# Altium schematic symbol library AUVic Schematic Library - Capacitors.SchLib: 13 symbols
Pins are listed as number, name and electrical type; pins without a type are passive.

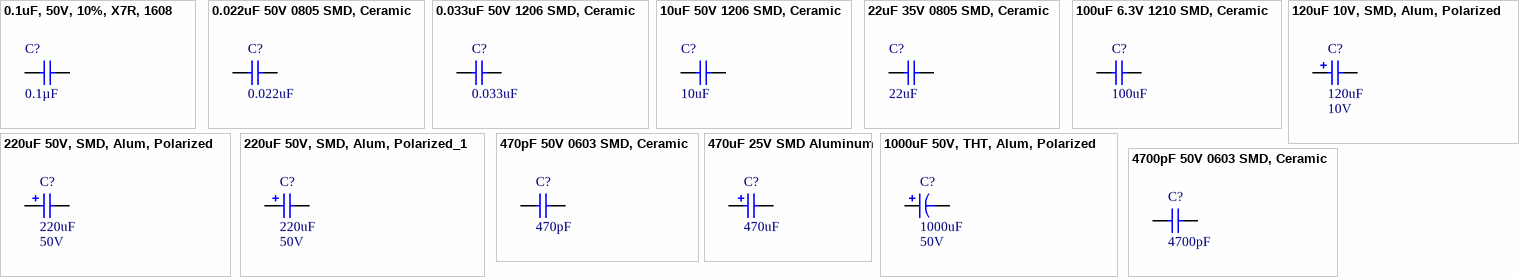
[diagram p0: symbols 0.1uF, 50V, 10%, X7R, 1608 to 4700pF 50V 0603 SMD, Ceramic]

## 0.1uF, 50V, 10%, X7R, 1608
designator C?  Capacitance: 0.1µF  (hidden comment: 0.1uF, 50V, 10%, X7R, 1608)
CAP CER 0.1UF 50V 10% X7R 1608 (0603); Manufacturer: Samsung Electro-Mechanics America, Inc; Manufacturer Part Number: CL10B104KB8SFNC; Description: CAP CER 0.1UF 50V 10% X7R 0603
footprint CAPC1608N(0603") (Chip Capacitor, Body 1.6x0.8mm (0603"), IPC Medium Density)
pins: 1, 2

## 0.022uF 50V 0805 SMD, Ceramic
designator C?, comment 0.022uF
Capacitor, Ceramic, 50V, +/-5%, 0805 SMD, X7R
footprint CAPC2012N(0805") (Chip Capacitor, Body 2.0x1.3mm (0805"), IPC Medium Density)
pins: 1, 2
1 alternate drawing of the same symbol

## 0.033uF 50V 1206 SMD, Ceramic
designator C?, comment 0.033uF
Capacitor, Ceramic, 50V, +/-1%, 1206 SMD, NP0
footprint CAPC3216N(1206") (Chip Capacitor, Body 3.2x1.6mm (1206"), IPC Medium Density)
pins: 1, 2
1 alternate drawing of the same symbol

## 10uF 50V 1206 SMD, Ceramic
designator C?, comment 10uF
Capacitor, Ceramic, 50V, +/- 10%, 1206 SMD, X5R
footprint CAPC3216N(1206") (Chip Capacitor, Body 3.2x1.6mm (1206"), IPC Medium Density)
pins: 1, 2
1 alternate drawing of the same symbol

## 22uF 35V 0805 SMD, Ceramic
designator C?, comment 22uF
Capacitor, Ceramic, 35V, +/- 20%, 0805 SMD, X5R
footprint CAPC2012N(0805") (Chip Capacitor, Body 2.0x1.3mm (0805"), IPC Medium Density)
pins: 1, 2
1 alternate drawing of the same symbol

## 100uF 6.3V 1210 SMD, Ceramic
designator C?, comment 100uF
Capacitor, Ceramic, 6.3V, +/- 10%, 1210 SMD, X5R
footprint CAPC3225N(1210") (Chip Capacitor, Body 3.2x2.5mm (1210"), IPC Medium Density)
pins: 1, 2
1 alternate drawing of the same symbol

## 120uF 10V, SMD, Alum, Polarized
designator C?, comment 120uF  Voltage: 10V
Capacitor, Polarized, Aluminum, 10V, +/- 20%, SMD, ESR: 25mOhm
footprint APXE100ARA121MF61G (Capacitor, SMD, Digi#565-3200-1-ND, United Chemi-Con)
pins: 1, 2
1 alternate drawing of the same symbol

## 220uF 50V, SMD, Alum, Polarized
designator C?, comment 220uF  Voltage: 50V
Capacitor, Polarized, Aluminum, 50V, +/- 20%, SMD
footprint EEE-1HA221P (Capacitor, SMD, Digi#PCE3921CT-ND, Panasonic-ECG)
pins: 1, 2
1 alternate drawing of the same symbol

## 220uF 50V, SMD, Alum, Polarized_1
designator C?, comment 220uF  Voltage: 50V
Capacitor, Polarized, Aluminum, 50V, +/- 20%, SMD
footprint EEE-1HA221P (Capacitor, SMD, Digi#PCE3921CT-ND, Panasonic-ECG)
pins: 1, 2
1 alternate drawing of the same symbol

## 470pF 50V 0603 SMD, Ceramic
designator C?, comment 470pF
Capacitor, Ceramic, 50V, +/- 10%, 0603 SMD, X7R
footprint CAPC1608N(0603") (Chip Capacitor, Body 1.6x0.8mm (0603"), IPC Medium Density)
pins: 1, 2
1 alternate drawing of the same symbol

## 470uF 25V SMD Aluminum
designator C?, comment 470uF
Capacitor, Polarized, Aluminum, 25V
footprint EEE-1HA221P (Capacitor, SMD, Digi#PCE3921CT-ND, Panasonic-ECG)
pins: 1, 2
1 alternate drawing of the same symbol

## 1000uF 50V, THT, Alum, Polarized
designator C?, comment 1000uF  Voltage: 50V
Capacitor, Polarized, Aluminum, 50V, +/- 20%, THT
footprint P5186-ND (Capacitor, THT, Digi#732-1209-1-ND, Panasonic-ECG)
pins: 1, 2
1 alternate drawing of the same symbol

## 4700pF 50V 0603 SMD, Ceramic
designator C?, comment 4700pF
Capacitor, Ceramic, 50V, +/-5%, 0603 SMD, NP0
footprint CAPC1608N(0603") (Chip Capacitor, Body 1.6x0.8mm (0603"), IPC Medium Density)
pins: 1, 2
1 alternate drawing of the same symbol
